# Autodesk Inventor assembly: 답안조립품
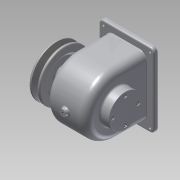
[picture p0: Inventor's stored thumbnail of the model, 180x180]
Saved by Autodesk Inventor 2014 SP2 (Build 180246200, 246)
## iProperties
Created: 2016-01
Part Number: 답안조립품
Document SubType Name: Assembly
Designer: Administrator
Author: Administrator
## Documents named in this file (16)
- C:\Users\Administrator\Desktop\460105V1001\답안조립품.iam
- C:\Users\Administrator\Desktop\460105V1001\V-벨트풀리.ipt
- C:\Users\Administrator\Desktop\460105V1001\뒤커버.ipt
- C:\Users\Administrator\Desktop\460105V1001\멈춤나사 - M4x10.ipt
- C:\Users\Administrator\Desktop\460105V1001\베어링 6203.ipt
- C:\Users\Administrator\Desktop\460105V1001\본체.ipt
- C:\Users\Administrator\Desktop\460105V1001\볼트 M3 x 8.ipt
- C:\Users\Administrator\Desktop\460105V1001\볼트 M3 x 10.ipt
- C:\Users\Administrator\Desktop\460105V1001\부시1.ipt
- C:\Users\Administrator\Desktop\460105V1001\부시2.ipt
- C:\Users\Administrator\Desktop\460105V1001\스퍼기어.ipt
- C:\Users\Administrator\Desktop\460105V1001\앞커버.ipt
- C:\Users\Administrator\Desktop\460105V1001\오일씰 28 40 8.ipt
- C:\Users\Administrator\Desktop\460105V1001\축.ipt
- C:\Users\Administrator\Desktop\460105V1001\키 - 5 x 5 x 18.ipt
- C:\Users\Administrator\Desktop\460105V1001\키 - 6 x 6 x 22.ipt
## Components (9 placed, 3 different names)
1. V-벨트풀리:1
2. ISO 4762 M3 x 8:1
3. ISO 4762 M3 x 8:2
4. ISO 4762 M3 x 8:3
5. ISO 4762 M3 x 8:4
6. ISO 4762 M3 x 10:1
7. ISO 4762 M3 x 10:2
8. ISO 4762 M3 x 10:3
9. ISO 4762 M3 x 10:4
